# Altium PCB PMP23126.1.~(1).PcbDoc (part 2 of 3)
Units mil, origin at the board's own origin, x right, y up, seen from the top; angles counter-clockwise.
Board outline 1315.03 x 1390.8 mil, 6 copper layers (Top Layer, MidLayer1, MidLayer2, MidLayer3, MidLayer4, Bottom Layer), stack 78 mil thick; 49 components, 55 nets, 222 pads, 193 vias.
Unrouted connection lines stored in the file: 15.
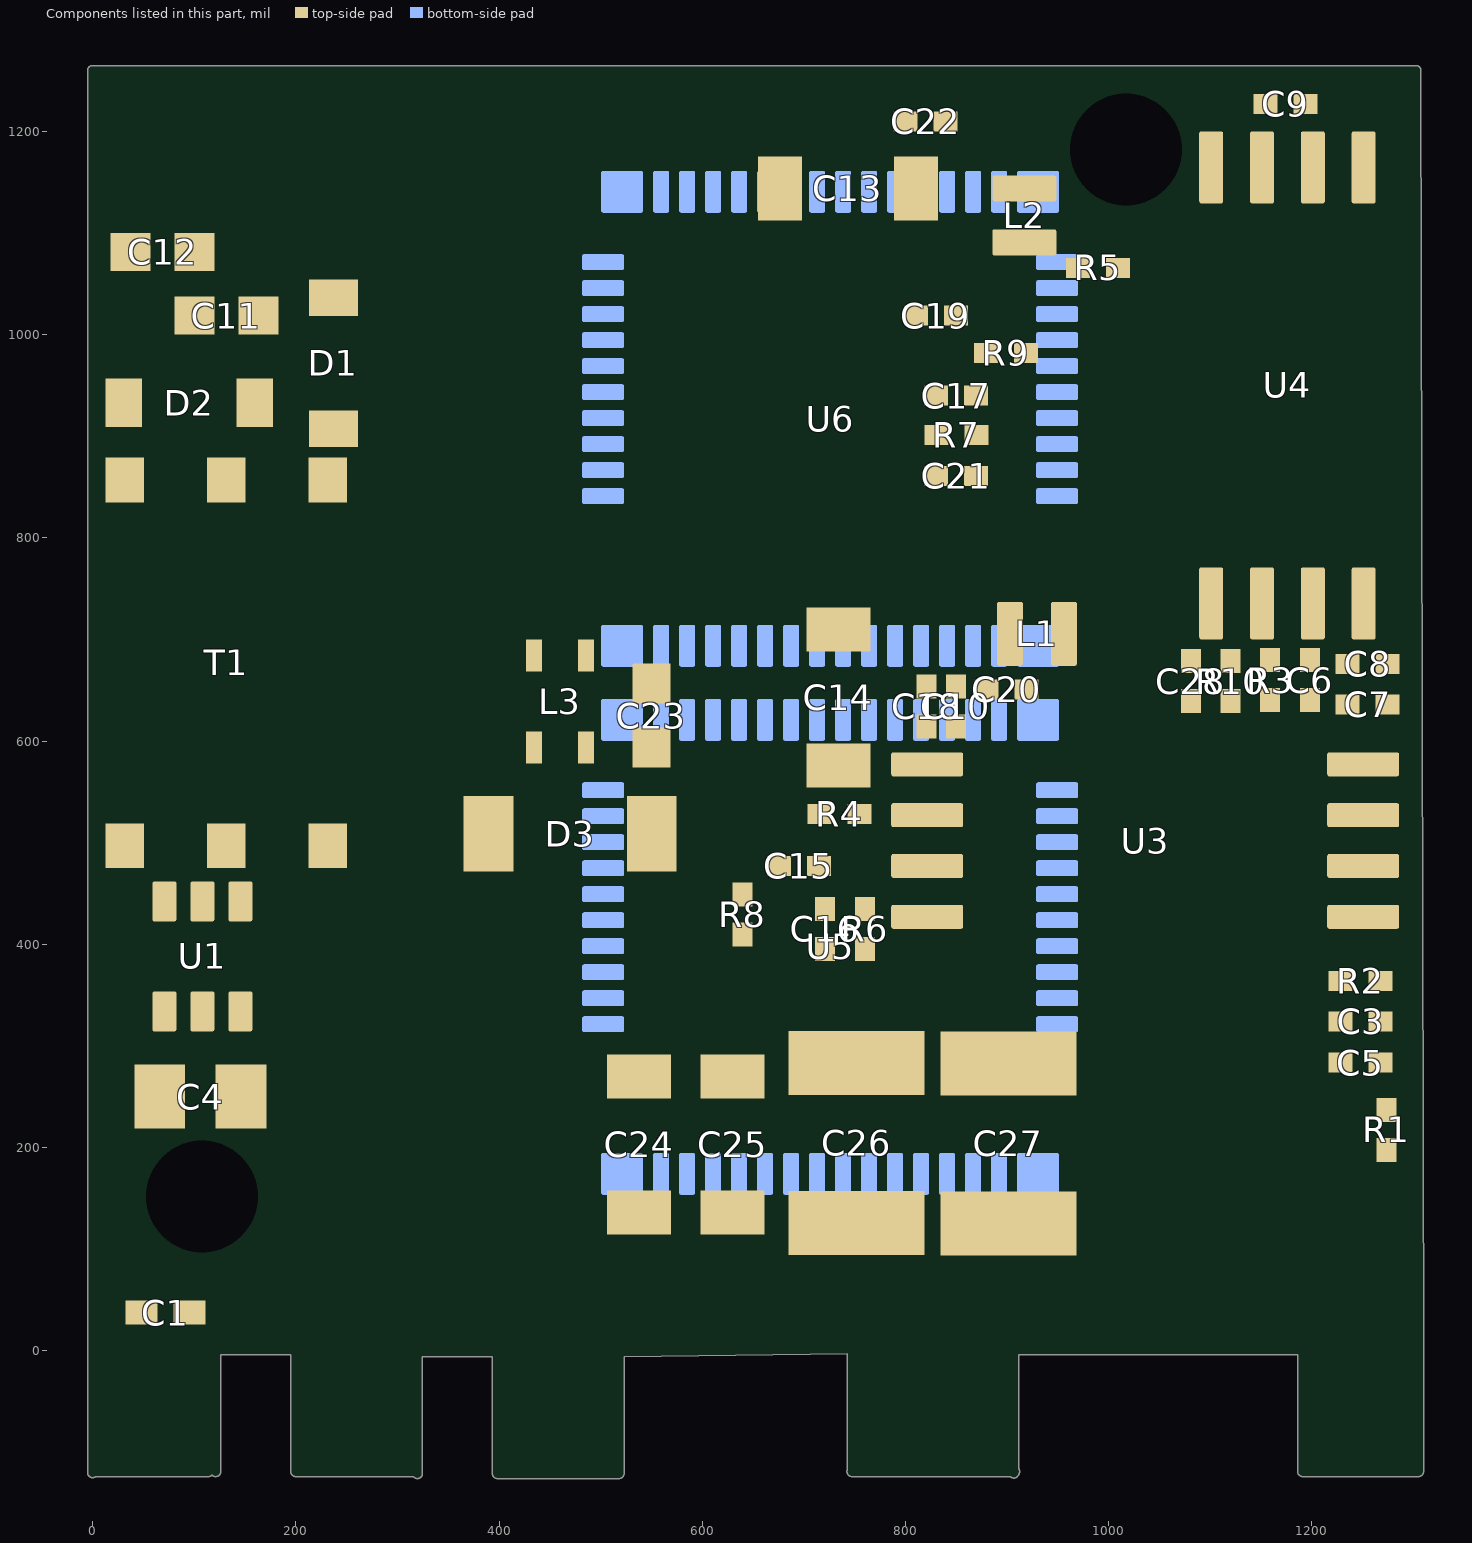
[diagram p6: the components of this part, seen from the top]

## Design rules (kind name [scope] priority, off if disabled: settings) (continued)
PolygonConnect PolygonConnect_38 [All vs IsNamedPolygon('SWNODE') Or  IsNamedPolygon('D403_2') Or  IsNamedPolygon('D403_2') Or  IsNamedPolygon('PGND') Or  IsNamedPolygon('BOTTOM_LAYER_NETC106_2_P030') Or  IsNamedPolygon('C102_1') Or  IsNamedPolygon('SGND') Or  IsNamedPolygon('TOP_LAYER_54V1_P046') Or  IsNamedPolygon('TOP_LAYER_54V2_P048') Or  IsNamedPolygon('TOP_LAYER_54V2_P048') Or  IsNamedPolygon('C108_1') Or  IsNamedPolygon('C108_1') Or  IsNamedPolygon('C108_1') Or  IsNamedPolygon('C108_1') Or  IsNamedPolygon('C108_1') Or  IsNamedPolygon('C108_1') Or  IsNamedPolygon('PGND') Or  IsNamedPolygon('ZCD') Or  IsNamedPolygon('Line') Or  IsNamedPolygon('5Vp') Or  IsNamedPolygon('12Vp') Or  IsNamedPolygon('T200_4') Or  IsNamedPolygon('T200_6') Or  IsNamedPolygon('SWNODE3') Or  IsNamedPolygon('T200_4') Or  IsNamedPolygon('T200_6') Or  IsNamedPolygon('SWNODE4') Or  IsNamedPolygon('VSR') Or  IsNamedPolygon('Iout_SNS') Or  IsNamedPolygon('SIGNAL_LAYER_2_VBB_P094') Or  IsNamedPolygon('Vbulk1') Or  IsNamedPolygon('VBB') Or  IsNamedPolygon('SIGNAL_LAYER_1_VBULK1_P106') Or  IsNamedPolygon('Line') Or  IsNamedPolygon('Line') Or  IsNamedPolygon('Line') Or  IsNamedPolygon('D404_2') Or  IsNamedPolygon('VBB') Or  IsNamedPolygon('D400_2') Or  IsNamedPolygon('SGND') Or  IsNamedPolygon('PGND') Or  IsNamedPolygon('TOP_LAYER_12VS_P126') Or  IsNamedPolygon('BOTTOM_LAYER_54V1_P128') Or  IsNamedPolygon('LEG3_HS_DRV') Or  IsNamedPolygon('LEG4_LS_DRV') Or  IsNamedPolygon('LEG4_HS_DRV') Or  IsNamedPolygon('SWNODE4') Or  IsNamedPolygon('SWNODE3') Or  IsNamedPolygon('T200_6') Or  IsNamedPolygon('T200_4') Or  IsNamedPolygon('VBB') Or  IsNamedPolygon('5Vs') Or  IsNamedPolygon('SGND') Or  IsNamedPolygon('Iout_SNS') Or  IsNamedPolygon('SGND') Or  IsNamedPolygon('SWNODE3') Or  IsNamedPolygon('SWNODE3') Or  IsNamedPolygon('SWNODE3') Or  IsNamedPolygon('SWNODE3') Or  IsNamedPolygon('SGND') Or  IsNamedPolygon('SGND') Or  IsNamedPolygon('SGND') Or  IsNamedPolygon('SWNODE4') Or  IsNamedPolygon('SWNODE4') Or  IsNamedPolygon('SWNODE4') Or  IsNamedPolygon('VSR') Or  IsNamedPolygon('SWNODE3') Or  IsNamedPolygon('SGND') Or  IsNamedPolygon('SGND') Or  IsNamedPolygon('SGND') Or  IsNamedPolygon('SGND') Or  IsNamedPolygon('SGND') Or  IsNamedPolygon('SGND') Or  IsNamedPolygon('BOTTOM_LAYER_54V1_P128') Or  IsNamedPolygon('SGND') Or  IsNamedPolygon('VSR') Or  IsNamedPolygon('C102_1') Or  IsNamedPolygon('C102_1') Or  IsNamedPolygon('C102_1') Or  IsNamedPolygon('C102_1') Or  IsNamedPolygon('C102_1') Or  IsNamedPolygon('ZCD') Or  IsNamedPolygon('PGND') Or  IsNamedPolygon('PGND') Or  IsNamedPolygon('Vbulk1') Or  IsNamedPolygon('VBB') Or  IsNamedPolygon('Vbulk1') Or  IsNamedPolygon('Vbulk1') Or  IsNamedPolygon('ZCD') Or  IsNamedPolygon('Neutral') Or  IsNamedPolygon('Neutral')] p22: connectstyle=Direct reliefconductorwidth=10 reliefentries=4 polygonreliefangle="90 Angle" airgapwidth=10
PolygonConnect PolygonConnect_37 [All vs IsNamedPolygon('SGND') Or  IsNamedPolygon('SWNODE4') Or  IsNamedPolygon('5Vp') Or  IsNamedPolygon('SWNODE4') Or  IsNamedPolygon('VBB') Or  IsNamedPolygon('Line') Or  IsNamedPolygon('SGND') Or  IsNamedPolygon('SIGNAL_LAYER_2_C102_1_P032') Or  IsNamedPolygon('TOP_LAYER_54V2_P048') Or  IsNamedPolygon('ZCD') Or  IsNamedPolygon('PGND') Or  IsNamedPolygon('SIGNAL_LAYER_2_VBB_P094') Or  IsNamedPolygon('Line') Or  IsNamedPolygon('Line') Or  IsNamedPolygon('D404_2') Or  IsNamedPolygon('PGND') Or  IsNamedPolygon('SIGNAL_LAYER_1_ZCD_P108') Or  IsNamedPolygon('SWNODE3') Or  IsNamedPolygon('SIGNAL_LAYER_4_C102_1_P038') Or  IsNamedPolygon('SWNODE3') Or  IsNamedPolygon('LEG4_HS_DRV') Or  IsNamedPolygon('SWNODE4') Or  IsNamedPolygon('5Vs') Or  IsNamedPolygon('VBB') Or  IsNamedPolygon('TOP_LAYER_54V2_P048') Or  IsNamedPolygon('C102_1') Or  IsNamedPolygon('LEG4_LS_DRV') Or  IsNamedPolygon('T200_4') Or  IsNamedPolygon('SWNODE3') Or  IsNamedPolygon('Line') Or  IsNamedPolygon('SGND') Or  IsNamedPolygon('SGND') Or  IsNamedPolygon('SWNODE4') Or  IsNamedPolygon('12Vp') Or  IsNamedPolygon('BOTTOM_LAYER_NETC106_2_P030') Or  IsNamedPolygon('T200_4') Or  IsNamedPolygon('Vbulk1') Or  IsNamedPolygon('C108_1') Or  IsNamedPolygon('BOTTOM_LAYER_54V1_P128') Or  IsNamedPolygon('BOTTOM_LAYER_54V1_P128') Or  IsNamedPolygon('SWNODE') Or  IsNamedPolygon('Iout_SNS') Or  IsNamedPolygon('VSR') Or  IsNamedPolygon('D400_2') Or  IsNamedPolygon('D403_2') Or  IsNamedPolygon('SWNODE3') Or  IsNamedPolygon('T200_6') Or  IsNamedPolygon('SWNODE3') Or  IsNamedPolygon('C108_1') Or  IsNamedPolygon('PGND') Or  IsNamedPolygon('BOTTOM_LAYER_VBULK1_P096') Or  IsNamedPolygon('BOTTOM_LAYER_54V1_P128') Or  IsNamedPolygon('TOP_LAYER_12VS_P126') Or  IsNamedPolygon('SIGNAL_LAYER_1_VBULK1_P106') Or  IsNamedPolygon('T200_4') Or  IsNamedPolygon('SGND') Or  IsNamedPolygon('C108_1') Or  IsNamedPolygon('SWNODE3') Or  IsNamedPolygon('T200_6') Or  IsNamedPolygon('T200_6') Or  IsNamedPolygon('T200_6') Or  IsNamedPolygon('SGND') Or  IsNamedPolygon('C108_1') Or  IsNamedPolygon('SGND') Or  IsNamedPolygon('VBB') Or  IsNamedPolygon('T200_4') Or  IsNamedPolygon('LEG3_HS_DRV') Or  IsNamedPolygon('C108_1') Or  IsNamedPolygon('D403_2') Or  IsNamedPolygon('Iout_SNS') Or  IsNamedPolygon('C108_1') Or  IsNamedPolygon('SWNODE4')] p23: connectstyle=Direct reliefconductorwidth=10 reliefentries=4 polygonreliefangle="90 Angle" airgapwidth=10
PolygonConnect PolygonConnect_36 [All vs IsNamedPolygon('PGND') Or  IsNamedPolygon('BOTTOM_LAYER_54V1_P128') Or  IsNamedPolygon('SGND') Or  IsNamedPolygon('LEG4_LS_DRV') Or  IsNamedPolygon('TOP_LAYER_12VS_P126') Or  IsNamedPolygon('LEG4_HS_DRV') Or  IsNamedPolygon('LEG3_HS_DRV') Or  IsNamedPolygon('SGND') Or  IsNamedPolygon('C108_1') Or  IsNamedPolygon('12Vp') Or  IsNamedPolygon('D403_2') Or  IsNamedPolygon('SIGNAL_LAYER_1_ZCD_P108') Or  IsNamedPolygon('C108_1') Or  IsNamedPolygon('BOTTOM_LAYER_VBULK1_P096') Or  IsNamedPolygon('SWNODE') Or  IsNamedPolygon('T200_4') Or  IsNamedPolygon('D400_2') Or  IsNamedPolygon('C102_1') Or  IsNamedPolygon('Line') Or  IsNamedPolygon('VBB') Or  IsNamedPolygon('Line') Or  IsNamedPolygon('TOP_LAYER_54V2_P048') Or  IsNamedPolygon('BOTTOM_LAYER_NETC106_2_P030') Or  IsNamedPolygon('SIGNAL_LAYER_1_VBULK1_P106') Or  IsNamedPolygon('Line') Or  IsNamedPolygon('5Vp') Or  IsNamedPolygon('BOTTOM_LAYER_54V1_P128') Or  IsNamedPolygon('D404_2') Or  IsNamedPolygon('C108_1') Or  IsNamedPolygon('VSR') Or  IsNamedPolygon('T200_6') Or  IsNamedPolygon('VBB') Or  IsNamedPolygon('C108_1') Or  IsNamedPolygon('SIGNAL_LAYER_2_C102_1_P032') Or  IsNamedPolygon('SGND') Or  IsNamedPolygon('PGND') Or  IsNamedPolygon('SIGNAL_LAYER_4_C102_1_P038') Or  IsNamedPolygon('Vbulk1') Or  IsNamedPolygon('TOP_LAYER_54V2_P048') Or  IsNamedPolygon('Iout_SNS') Or  IsNamedPolygon('PGND') Or  IsNamedPolygon('T200_4') Or  IsNamedPolygon('ZCD') Or  IsNamedPolygon('Line') Or  IsNamedPolygon('C108_1') Or  IsNamedPolygon('D403_2') Or  IsNamedPolygon('SIGNAL_LAYER_2_VBB_P094') Or  IsNamedPolygon('SGND') Or  IsNamedPolygon('C108_1') Or  IsNamedPolygon('SIGNAL_LAYER_1_IOUT_SNS_P044') Or  IsNamedPolygon('BOTTOM_LAYER_54V1_P128') Or  IsNamedPolygon('T200_6')] p24: connectstyle=Direct reliefconductorwidth=10 reliefentries=4 polygonreliefangle="90 Angle" airgapwidth=10
PolygonConnect PolygonConnect_35 [All vs IsNamedPolygon('SWNODE') Or  IsNamedPolygon('D403_2') Or  IsNamedPolygon('D403_2') Or  IsNamedPolygon('PGND') Or  IsNamedPolygon('BOTTOM_LAYER_NETC106_2_P030') Or  IsNamedPolygon('SIGNAL_LAYER_2_C102_1_P032') Or  IsNamedPolygon('C102_1') Or  IsNamedPolygon('SIGNAL_LAYER_4_C102_1_P038') Or  IsNamedPolygon('SGND') Or  IsNamedPolygon('SIGNAL_LAYER_1_IOUT_SNS_P044') Or  IsNamedPolygon('BOTTOM_LAYER_54V1_P128') Or  IsNamedPolygon('TOP_LAYER_54V2_P048') Or  IsNamedPolygon('BOTTOM_LAYER_54V1_P128') Or  IsNamedPolygon('TOP_LAYER_54V2_P048') Or  IsNamedPolygon('C108_1') Or  IsNamedPolygon('C108_1') Or  IsNamedPolygon('C108_1') Or  IsNamedPolygon('C108_1') Or  IsNamedPolygon('C108_1') Or  IsNamedPolygon('C108_1') Or  IsNamedPolygon('PGND') Or  IsNamedPolygon('ZCD') Or  IsNamedPolygon('Line') Or  IsNamedPolygon('5Vp') Or  IsNamedPolygon('12Vp') Or  IsNamedPolygon('T200_4') Or  IsNamedPolygon('T200_6') Or  IsNamedPolygon('SGND') Or  IsNamedPolygon('T200_4') Or  IsNamedPolygon('T200_6') Or  IsNamedPolygon('SGND') Or  IsNamedPolygon('VSR') Or  IsNamedPolygon('Iout_SNS') Or  IsNamedPolygon('SIGNAL_LAYER_2_VBB_P094') Or  IsNamedPolygon('BOTTOM_LAYER_VBULK1_P096') Or  IsNamedPolygon('Vbulk1') Or  IsNamedPolygon('VBB') Or  IsNamedPolygon('SIGNAL_LAYER_1_VBULK1_P106') Or  IsNamedPolygon('SIGNAL_LAYER_1_ZCD_P108') Or  IsNamedPolygon('Line') Or  IsNamedPolygon('Line') Or  IsNamedPolygon('Line') Or  IsNamedPolygon('D404_2') Or  IsNamedPolygon('VBB') Or  IsNamedPolygon('D400_2') Or  IsNamedPolygon('SGND') Or  IsNamedPolygon('PGND') Or  IsNamedPolygon('TOP_LAYER_12VS_P126') Or  IsNamedPolygon('BOTTOM_LAYER_54V1_P128') Or  IsNamedPolygon('LEG3_HS_DRV')] p25: connectstyle=Direct reliefconductorwidth=10 reliefentries=4 polygonreliefangle="90 Angle" airgapwidth=10
PolygonConnect PolygonConnect_34 [All vs IsNamedPolygon('SWNODE') Or  IsNamedPolygon('D403_2') Or  IsNamedPolygon('D403_2') Or  IsNamedPolygon('PGND') Or  IsNamedPolygon('BOTTOM_LAYER_NETC106_2_P030') Or  IsNamedPolygon('SIGNAL_LAYER_2_C102_1_P032') Or  IsNamedPolygon('C102_1') Or  IsNamedPolygon('SIGNAL_LAYER_4_C102_1_P038') Or  IsNamedPolygon('SGND') Or  IsNamedPolygon('SIGNAL_LAYER_1_IOUT_SNS_P044') Or  IsNamedPolygon('BOTTOM_LAYER_54V1_P128') Or  IsNamedPolygon('TOP_LAYER_54V2_P048') Or  IsNamedPolygon('BOTTOM_LAYER_54V1_P128') Or  IsNamedPolygon('TOP_LAYER_54V2_P048') Or  IsNamedPolygon('C108_1') Or  IsNamedPolygon('C108_1') Or  IsNamedPolygon('C108_1') Or  IsNamedPolygon('C108_1') Or  IsNamedPolygon('C108_1') Or  IsNamedPolygon('C108_1') Or  IsNamedPolygon('PGND') Or  IsNamedPolygon('ZCD') Or  IsNamedPolygon('Line') Or  IsNamedPolygon('5Vp') Or  IsNamedPolygon('12Vp') Or  IsNamedPolygon('T200_4') Or  IsNamedPolygon('T200_6') Or  IsNamedPolygon('SGND') Or  IsNamedPolygon('T200_4') Or  IsNamedPolygon('T200_6') Or  IsNamedPolygon('SGND') Or  IsNamedPolygon('VSR') Or  IsNamedPolygon('Iout_SNS') Or  IsNamedPolygon('SIGNAL_LAYER_2_VBB_P094') Or  IsNamedPolygon('BOTTOM_LAYER_VBULK1_P096') Or  IsNamedPolygon('Vbulk1') Or  IsNamedPolygon('VBB') Or  IsNamedPolygon('SIGNAL_LAYER_1_VBULK1_P106') Or  IsNamedPolygon('SIGNAL_LAYER_1_ZCD_P108') Or  IsNamedPolygon('Line') Or  IsNamedPolygon('Line') Or  IsNamedPolygon('Line') Or  IsNamedPolygon('D404_2') Or  IsNamedPolygon('VBB') Or  IsNamedPolygon('D400_2') Or  IsNamedPolygon('SGND')] p26: connectstyle=Direct reliefconductorwidth=10 reliefentries=4 polygonreliefangle="90 Angle" airgapwidth=10
PolygonConnect PolygonConnect_33 [All vs IsNamedPolygon('SIGNAL_LAYER_1_VBULK1_P106')] p27: connectstyle=Direct reliefconductorwidth=10 reliefentries=4 polygonreliefangle="90 Angle" airgapwidth=10
PolygonConnect PolygonConnect_32 [All vs IsNamedPolygon('SIGNAL_LAYER_1_VBULK1_P106')] p28: connectstyle=Direct reliefconductorwidth=10 reliefentries=4 polygonreliefangle="90 Angle" airgapwidth=10
PolygonConnect PolygonConnect_31 [All vs IsNamedPolygon('SIGNAL_LAYER_1_VBULK1_P106')] p29: connectstyle=Direct reliefconductorwidth=10 reliefentries=4 polygonreliefangle="90 Angle" airgapwidth=10
PolygonConnect PolygonConnect_30 [All vs IsNamedPolygon('VBB')] p30: connectstyle=Direct reliefconductorwidth=10 reliefentries=4 polygonreliefangle="90 Angle" airgapwidth=10
PolygonConnect PolygonConnect_29 [All vs IsNamedPolygon('SGND')] p31: connectstyle=Direct reliefconductorwidth=10 reliefentries=4 polygonreliefangle="90 Angle" airgapwidth=10
PolygonConnect PolygonConnect_28 [All vs IsNamedPolygon('Vbulk1')] p32: connectstyle=Direct reliefconductorwidth=10 reliefentries=4 polygonreliefangle="90 Angle" airgapwidth=10
PolygonConnect PolygonConnect_27 [All vs IsNamedPolygon('BOTTOM_LAYER_VBULK1_P096')] p33: connectstyle=Direct reliefconductorwidth=10 reliefentries=4 polygonreliefangle="90 Angle" airgapwidth=10
PolygonConnect PolygonConnect_26 [All vs IsNamedPolygon('SIGNAL_LAYER_2_VBB_P094')] p34: connectstyle=Direct reliefconductorwidth=10 reliefentries=4 polygonreliefangle="90 Angle" airgapwidth=10
PolygonConnect PolygonConnect_25 [All vs IsNamedPolygon('C108_1')] p35: connectstyle=Direct reliefconductorwidth=10 reliefentries=4 polygonreliefangle="90 Angle" airgapwidth=10
PolygonConnect PolygonConnect_24 [All vs IsNamedPolygon('BOTTOM_LAYER_EARTH_P100')] p36: connectstyle=Direct reliefconductorwidth=10 reliefentries=4 polygonreliefangle="90 Angle" airgapwidth=10
PolygonConnect PolygonConnect_23 [All vs IsNamedPolygon('BOTTOM_LAYER_54V1_P128')] p37: connectstyle=Direct reliefconductorwidth=10 reliefentries=4 polygonreliefangle="90 Angle" airgapwidth=10
PolygonConnect PolygonConnect_22 [All vs IsNamedPolygon('BOTTOM_LAYER_VBULK1_P096')] p38: connectstyle=Direct reliefconductorwidth=10 reliefentries=4 polygonreliefangle="90 Angle" airgapwidth=10
PolygonConnect PolygonConnect_21 [All vs IsNamedPolygon('SIGNAL_LAYER_2_VBB_P094')] p39: connectstyle=Direct reliefconductorwidth=10 reliefentries=4 polygonreliefangle="90 Angle" airgapwidth=10
PolygonConnect PolygonConnect_20 [All vs IsNamedPolygon('Iout_SNS')] p40: connectstyle=Direct reliefconductorwidth=10 reliefentries=4 polygonreliefangle="90 Angle" airgapwidth=10
PolygonConnect PolygonConnect_19 [All vs IsNamedPolygon('C108_1') Or  IsNamedPolygon('BOTTOM_LAYER_NETC106_2_P030') Or  IsNamedPolygon('D403_2') Or  IsNamedPolygon('C102_1') Or  IsNamedPolygon('SWNODE') Or  IsNamedPolygon('D403_2') Or  IsNamedPolygon('SIGNAL_LAYER_4_C102_1_P038') Or  IsNamedPolygon('PGND') Or  IsNamedPolygon('SIGNAL_LAYER_2_C102_1_P032') Or  IsNamedPolygon('SIGNAL_LAYER_1_IOUT_SNS_P044') Or  IsNamedPolygon('SGND') Or  IsNamedPolygon('C108_1') Or  IsNamedPolygon('BOTTOM_LAYER_54V1_P128') Or  IsNamedPolygon('C108_1') Or  IsNamedPolygon('C108_1') Or  IsNamedPolygon('TOP_LAYER_54V2_P048') Or  IsNamedPolygon('BOTTOM_LAYER_54V1_P128') Or  IsNamedPolygon('TOP_LAYER_54V2_P048') Or  IsNamedPolygon('C108_1') Or  IsNamedPolygon('C108_1') Or  IsNamedPolygon('12Vp') Or  IsNamedPolygon('5Vp') Or  IsNamedPolygon('Line') Or  IsNamedPolygon('T200_4') Or  IsNamedPolygon('SGND') Or  IsNamedPolygon('VSR') Or  IsNamedPolygon('ZCD') Or  IsNamedPolygon('PGND') Or  IsNamedPolygon('T200_6') Or  IsNamedPolygon('Neutral') Or  IsNamedPolygon('T200_4') Or  IsNamedPolygon('SGND') Or  IsNamedPolygon('T200_6')] p41: connectstyle=Direct reliefconductorwidth=10 reliefentries=4 polygonreliefangle="90 Angle" airgapwidth=10
PolygonConnect PolygonConnect_18 [All vs IsNamedPolygon('SWNODE') Or  IsNamedPolygon('D403_2') Or  IsNamedPolygon('D403_2') Or  IsNamedPolygon('PGND') Or  IsNamedPolygon('BOTTOM_LAYER_NETC106_2_P030') Or  IsNamedPolygon('SIGNAL_LAYER_2_C102_1_P032') Or  IsNamedPolygon('C102_1') Or  IsNamedPolygon('SIGNAL_LAYER_4_C102_1_P038') Or  IsNamedPolygon('SGND') Or  IsNamedPolygon('SIGNAL_LAYER_1_IOUT_SNS_P044') Or  IsNamedPolygon('BOTTOM_LAYER_54V1_P128') Or  IsNamedPolygon('TOP_LAYER_54V2_P048') Or  IsNamedPolygon('BOTTOM_LAYER_54V1_P128') Or  IsNamedPolygon('TOP_LAYER_54V2_P048') Or  IsNamedPolygon('C108_1') Or  IsNamedPolygon('C108_1') Or  IsNamedPolygon('C108_1') Or  IsNamedPolygon('C108_1') Or  IsNamedPolygon('C108_1') Or  IsNamedPolygon('C108_1') Or  IsNamedPolygon('Neutral') Or  IsNamedPolygon('PGND') Or  IsNamedPolygon('ZCD') Or  IsNamedPolygon('Line') Or  IsNamedPolygon('5Vp') Or  IsNamedPolygon('12Vp') Or  IsNamedPolygon('T200_4') Or  IsNamedPolygon('T200_6') Or  IsNamedPolygon('SGND') Or  IsNamedPolygon('T200_4') Or  IsNamedPolygon('T200_6') Or  IsNamedPolygon('SGND')] p42: connectstyle=Direct reliefconductorwidth=10 reliefentries=4 polygonreliefangle="90 Angle" airgapwidth=10
PolygonConnect PolygonConnect_17 [All vs IsNamedPolygon('12Vp') Or  IsNamedPolygon('T200_4') Or  IsNamedPolygon('T200_6') Or  IsNamedPolygon('SGND') Or  IsNamedPolygon('TOP_LAYER_54V2_P048') Or  IsNamedPolygon('SIGNAL_LAYER_1_IOUT_SNS_P044') Or  IsNamedPolygon('BOTTOM_LAYER_54V1_P128') Or  IsNamedPolygon('SGND') Or  IsNamedPolygon('C102_1') Or  IsNamedPolygon('SIGNAL_LAYER_4_C102_1_P038') Or  IsNamedPolygon('Neutral') Or  IsNamedPolygon('C108_1') Or  IsNamedPolygon('C108_1') Or  IsNamedPolygon('C108_1') Or  IsNamedPolygon('BOTTOM_LAYER_54V1_P128') Or  IsNamedPolygon('TOP_LAYER_54V2_P048') Or  IsNamedPolygon('SIGNAL_LAYER_2_C102_1_P032') Or  IsNamedPolygon('SWNODE') Or  IsNamedPolygon('C108_1') Or  IsNamedPolygon('C108_1') Or  IsNamedPolygon('C108_1') Or  IsNamedPolygon('D403_2') Or  IsNamedPolygon('BOTTOM_LAYER_NETC106_2_P030') Or  IsNamedPolygon('PGND') Or  IsNamedPolygon('D403_2') Or  IsNamedPolygon('5Vp') Or  IsNamedPolygon('PGND') Or  IsNamedPolygon('ZCD') Or  IsNamedPolygon('Line')] p43: connectstyle=Direct reliefconductorwidth=10 reliefentries=4 polygonreliefangle="90 Angle" airgapwidth=10
PolygonConnect PolygonConnect_16 [All vs IsNamedPolygon('D403_2') Or  IsNamedPolygon('C102_1') Or  IsNamedPolygon('C108_1') Or  IsNamedPolygon('SWNODE') Or  IsNamedPolygon('BOTTOM_LAYER_54V1_P128') Or  IsNamedPolygon('SGND') Or  IsNamedPolygon('Line') Or  IsNamedPolygon('ZCD') Or  IsNamedPolygon('SIGNAL_LAYER_1_IOUT_SNS_P044') Or  IsNamedPolygon('Neutral') Or  IsNamedPolygon('PGND') Or  IsNamedPolygon('12Vp') Or  IsNamedPolygon('C108_1') Or  IsNamedPolygon('C108_1') Or  IsNamedPolygon('TOP_LAYER_54V2_P048') Or  IsNamedPolygon('C108_1') Or  IsNamedPolygon('TOP_LAYER_54V2_P048') Or  IsNamedPolygon('T200_4') Or  IsNamedPolygon('T200_6') Or  IsNamedPolygon('D403_2') Or  IsNamedPolygon('C108_1') Or  IsNamedPolygon('C108_1') Or  IsNamedPolygon('SIGNAL_LAYER_4_C102_1_P038') Or  IsNamedPolygon('SIGNAL_LAYER_2_C102_1_P032') Or  IsNamedPolygon('PGND') Or  IsNamedPolygon('BOTTOM_LAYER_NETC106_2_P030') Or  IsNamedPolygon('5Vp') Or  IsNamedPolygon('BOTTOM_LAYER_54V1_P128')] p44: connectstyle=Direct reliefconductorwidth=10 reliefentries=4 polygonreliefangle="90 Angle" airgapwidth=10
PolygonConnect PolygonConnect_15 [All vs IsNamedPolygon('SWNODE') Or  IsNamedPolygon('D403_2') Or  IsNamedPolygon('D403_2') Or  IsNamedPolygon('SIGNAL_LAYER_1_PGND_P018') Or  IsNamedPolygon('PGND') Or  IsNamedPolygon('BOTTOM_LAYER_NETC106_2_P030') Or  IsNamedPolygon('SIGNAL_LAYER_2_C102_1_P032') Or  IsNamedPolygon('C102_1') Or  IsNamedPolygon('SIGNAL_LAYER_4_C102_1_P038') Or  IsNamedPolygon('SGND') Or  IsNamedPolygon('SIGNAL_LAYER_1_IOUT_SNS_P044') Or  IsNamedPolygon('BOTTOM_LAYER_54V1_P128') Or  IsNamedPolygon('TOP_LAYER_54V2_P048') Or  IsNamedPolygon('BOTTOM_LAYER_54V1_P128') Or  IsNamedPolygon('TOP_LAYER_54V2_P048') Or  IsNamedPolygon('C108_1') Or  IsNamedPolygon('C108_1') Or  IsNamedPolygon('C108_1') Or  IsNamedPolygon('C108_1') Or  IsNamedPolygon('C108_1') Or  IsNamedPolygon('C108_1') Or  IsNamedPolygon('Neutral') Or  IsNamedPolygon('PGND') Or  IsNamedPolygon('ZCD') Or  IsNamedPolygon('Line') Or  IsNamedPolygon('5Vp') Or  IsNamedPolygon('12Vp')] p45: connectstyle=Direct reliefconductorwidth=10 reliefentries=4 polygonreliefangle="90 Angle" airgapwidth=10
PolygonConnect PolygonConnect_14 [All vs IsNamedPolygon('TOP_LAYER_54V2_P048') Or  IsNamedPolygon('C108_1') Or  IsNamedPolygon('C108_1') Or  IsNamedPolygon('SIGNAL_LAYER_4_C102_1_P038') Or  IsNamedPolygon('C102_1') Or  IsNamedPolygon('SIGNAL_LAYER_2_C102_1_P032') Or  IsNamedPolygon('SIGNAL_LAYER_1_PGND_P018') Or  IsNamedPolygon('SIGNAL_LAYER_1_IOUT_SNS_P044') Or  IsNamedPolygon('SGND') Or  IsNamedPolygon('C108_1') Or  IsNamedPolygon('ZCD') Or  IsNamedPolygon('PGND') Or  IsNamedPolygon('TOP_LAYER_54V2_P048') Or  IsNamedPolygon('BOTTOM_LAYER_NETC106_2_P030') Or  IsNamedPolygon('PGND') Or  IsNamedPolygon('C108_1') Or  IsNamedPolygon('C108_1') Or  IsNamedPolygon('D403_2') Or  IsNamedPolygon('Line') Or  IsNamedPolygon('C108_1') Or  IsNamedPolygon('Neutral') Or  IsNamedPolygon('SWNODE') Or  IsNamedPolygon('D403_2') Or  IsNamedPolygon('BOTTOM_LAYER_54V1_P128') Or  IsNamedPolygon('BOTTOM_LAYER_54V1_P128')] p46: connectstyle=Direct reliefconductorwidth=10 reliefentries=4 polygonreliefangle="90 Angle" airgapwidth=10
PolygonConnect PolygonConnect_13 [All vs IsNamedPolygon('PGND') Or  IsNamedPolygon('D403_2') Or  IsNamedPolygon('SIGNAL_LAYER_1_PGND_P018') Or  IsNamedPolygon('D403_2') Or  IsNamedPolygon('SWNODE') Or  IsNamedPolygon('SGND') Or  IsNamedPolygon('BOTTOM_LAYER_54V1_P128') Or  IsNamedPolygon('C108_1') Or  IsNamedPolygon('SIGNAL_LAYER_4_C102_1_P038') Or  IsNamedPolygon('C108_1') Or  IsNamedPolygon('TOP_LAYER_54V2_P048') Or  IsNamedPolygon('TOP_LAYER_54V2_P048') Or  IsNamedPolygon('C108_1') Or  IsNamedPolygon('C108_1') Or  IsNamedPolygon('C108_1') Or  IsNamedPolygon('BOTTOM_LAYER_NETC106_2_P030') Or  IsNamedPolygon('SIGNAL_LAYER_1_IOUT_SNS_P044') Or  IsNamedPolygon('C108_1') Or  IsNamedPolygon('C102_1') Or  IsNamedPolygon('SIGNAL_LAYER_2_C102_1_P032') Or  IsNamedPolygon('BOTTOM_LAYER_54V1_P128')] p47: connectstyle=Direct reliefconductorwidth=10 reliefentries=4 polygonreliefangle="90 Angle" airgapwidth=10
PolygonConnect PolygonConnect_12 [All vs IsNamedPolygon('TOP_LAYER_54V2_P048')] p48: connectstyle=Direct reliefconductorwidth=10 reliefentries=4 polygonreliefangle="90 Angle" airgapwidth=10
PolygonConnect PolygonConnect_11 [All vs IsNamedPolygon('BOTTOM_LAYER_54V1_P128')] p49: connectstyle=Direct reliefconductorwidth=10 reliefentries=4 polygonreliefangle="90 Angle" airgapwidth=10
PolygonConnect PolygonConnect_10 [All vs IsNamedPolygon('SIGNAL_LAYER_1_IOUT_SNS_P044')] p50: thpad.connectstyle=Direct thpad.reliefconductorwidth=10 thpad.reliefentries=4 thpad.polygonreliefangle="90 Angle" thpad.airgapwidth=10 smdpad.connectstyle=Relief smdpad.reliefconductorwidth=10 smdpad.reliefentries=4 smdpad.polygonreliefangle="90 Angle" smdpad.airgapwidth=10 via.connectstyle=Direct via.reliefconductorwidth=10 via.reliefentries=4 via.polygonreliefangle="90 Angle" via.airgapwidth=10
PolygonConnect PolygonConnect_9 [All vs IsNamedPolygon('SGND')] p51: thpad.connectstyle=Direct thpad.reliefconductorwidth=10 thpad.reliefentries=4 thpad.polygonreliefangle="90 Angle" thpad.airgapwidth=10 smdpad.connectstyle=Relief smdpad.reliefconductorwidth=10 smdpad.reliefentries=4 smdpad.polygonreliefangle="90 Angle" smdpad.airgapwidth=10 via.connectstyle=Direct via.reliefconductorwidth=10 via.reliefentries=4 via.polygonreliefangle="90 Angle" via.airgapwidth=10
PolygonConnect PolygonConnect_8 [All vs IsNamedPolygon('SGND')] p52: thpad.connectstyle=Direct thpad.reliefconductorwidth=10 thpad.reliefentries=4 thpad.polygonreliefangle="90 Angle" thpad.airgapwidth=10 smdpad.connectstyle=Relief smdpad.reliefconductorwidth=10 smdpad.reliefentries=4 smdpad.polygonreliefangle="90 Angle" smdpad.airgapwidth=10 via.connectstyle=Direct via.reliefconductorwidth=10 via.reliefentries=4 via.polygonreliefangle="90 Angle" via.airgapwidth=10
PolygonConnect PolygonConnect_7 [All vs IsNamedPolygon('SGND')] p53: thpad.connectstyle=Relief thpad.reliefconductorwidth=0 thpad.reliefentries=4 thpad.polygonreliefangle="90 Angle" thpad.airgapwidth=0 smdpad.connectstyle=Relief smdpad.reliefconductorwidth=10 smdpad.reliefentries=4 smdpad.polygonreliefangle="90 Angle" smdpad.airgapwidth=10 via.connectstyle=Relief via.reliefconductorwidth=10 via.reliefentries=4 via.polygonreliefangle="90 Angle" via.airgapwidth=10
PolygonConnect PolygonConnect_6 [All vs IsNamedPolygon('SGND')] p54: thpad.connectstyle=Direct thpad.reliefconductorwidth=10 thpad.reliefentries=4 thpad.polygonreliefangle="90 Angle" thpad.airgapwidth=10 smdpad.connectstyle=Relief smdpad.reliefconductorwidth=10 smdpad.reliefentries=4 smdpad.polygonreliefangle="90 Angle" smdpad.airgapwidth=10 via.connectstyle=Relief via.reliefconductorwidth=10 via.reliefentries=4 via.polygonreliefangle="90 Angle" via.airgapwidth=10
PolygonConnect PolygonConnect_5 [All vs IsNamedPolygon('SGND')] p55: thpad.connectstyle=Direct thpad.reliefconductorwidth=10 thpad.reliefentries=4 thpad.polygonreliefangle="90 Angle" thpad.airgapwidth=10 smdpad.connectstyle=Relief smdpad.reliefconductorwidth=10 smdpad.reliefentries=4 smdpad.polygonreliefangle="90 Angle" smdpad.airgapwidth=10 via.connectstyle=Relief via.reliefconductorwidth=10 via.reliefentries=4 via.polygonreliefangle="90 Angle" via.airgapwidth=10
PolygonConnect PolygonConnect_4 [All vs IsNamedPolygon('SIGNAL_LAYER_1_PGND_P018') Or  IsNamedPolygon('SWNODE') Or  IsNamedPolygon('D403_2') Or  IsNamedPolygon('SIGNAL_LAYER_4_C102_1_P038') Or  IsNamedPolygon('D403_2') Or  IsNamedPolygon('BOTTOM_LAYER_NETC106_2_P030') Or  IsNamedPolygon('C102_1') Or  IsNamedPolygon('PGND') Or  IsNamedPolygon('SIGNAL_LAYER_2_C102_1_P032')] p56: connectstyle=Direct reliefconductorwidth=10 reliefentries=4 polygonreliefangle="90 Angle" airgapwidth=10
PolygonConnect PolygonConnect_3 [All vs IsNamedPolygon('SWNODE') Or  IsNamedPolygon('D403_2') Or  IsNamedPolygon('Neutral') Or  IsNamedPolygon('C106_2') Or  IsNamedPolygon('D403_2') Or  IsNamedPolygon('Neutral') Or  IsNamedPolygon('Neutral')] p57: connectstyle=Direct reliefconductorwidth=10 reliefentries=4 polygonreliefangle="90 Angle" airgapwidth=10
PolygonConnect PolygonConnect_2 [All vs IsNamedPolygon('Neutral') Or  IsNamedPolygon('Neutral') Or  IsNamedPolygon('C106_2') Or  IsNamedPolygon('SWNODE') Or  IsNamedPolygon('Neutral')] p58: connectstyle=Direct reliefconductorwidth=10 reliefentries=4 polygonreliefangle="90 Angle" airgapwidth=10
PolygonConnect PolygonConnect_1 [All vs IsNamedPolygon('Neutral') Or  IsNamedPolygon('Neutral')] p59: connectstyle=Direct reliefconductorwidth=10 reliefentries=4 polygonreliefangle="90 Angle" airgapwidth=10
PolygonConnect [All] p60: connectstyle=Direct reliefconductorwidth=10 reliefentries=4 polygonreliefangle="90 Angle" airgapwidth=10
RoutingVias ThermalPadVias [IsVia and InAnyComponent] p1: holewidth=7.87 width=19.68 viastyle="Through Hole" minholewidth=7.87 minwidth=19.68 maxholewidth=12.99 maxwidth=23.62
RoutingVias [All] p2: holewidth=10 width=34 viastyle="Through Hole" minholewidth=7.87 minwidth=19 maxholewidth=40 maxwidth=65
SilkToSilkClearance SilkToSilkClearance_Pb-FreeLogo [(HasFootprint('Pb-Free_Overlay_Medium') OR HasFootprint('Pb-Free_Overlay_Small')) vs (HasFootprint('Pb-Free_Overlay_Medium') OR HasFootprint('Pb-Free_Overlay_Small'))] p1: silktosilkclearance=0
SilkToSilkClearance [All] p2: silktosilkclearance=1
SilkToSolderMaskClearance SilkToComponentPadClearance [(IsPad or IsFill or IsRegion) and InAnycomponent] p1: minsilkscreentomaskgap=1 clearancetoexposedcopper=TRUE
SilkToSolderMaskClearance "Silk to Solder Mask Opening" [All] p2: minsilkscreentomaskgap=1 clearancetoexposedcopper=FALSE
SolderMaskExpansion [All] p1: expansion=1.97
Width [All] p1: maxlimit=100 minlimit=6 preferedwidth=10 checkconnectedcopper=TRUE
14 further rules are at their usual default settings.

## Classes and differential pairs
net class INGND: 3.3Vs _Bot_FET_FAULT1 _Top_FET_FAULT1 AGND LEG1_HS LEG1_LS NetC5_1 NetC6_1 NetR2_2 NetR10_2 NetU2_12 NetU3_12
net class PGND: 5V_L1 5Vp 12V FAULT_LS NetC17_2 NetC19_2 NetC22_1 NetL2_2 NetR5_1 NetR9_2 NetT1_4 NetT1_6 NetU2_5 NetU6_43 NetU6_47 NetU6_48 NetU6_52 PGND PGND_NC1 PGND_NC2 PGND_NC3 PGND_NC4 PGND_NC5 TEMP_LS
net class VHV: Vbulk+ VHV_NC1 VHV_NC2
net class VSW1NET: 5V_H1 12V ISO_12V_H1 NCT1 NetC11_1 NetC11_2 NetC12_2 NetC15_2 NetC16_2 NetC20_1 NetD1_2 NetL1_2 NetR4_2 NetR8_2 NetT1_5 NetU3_3 NetU3_5 NetU5_43 NetU5_47 NetU5_48 NetU5_52 SW1 SW1_NC1 SW1_NC2 SW1_NC3 SW1_NC4 SW1_NC5 SW1_NC6 SW1_NC7 TEMP_HS_NC1
component class LMG352X: U5 U6

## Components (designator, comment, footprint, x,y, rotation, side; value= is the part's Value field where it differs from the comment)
C1 "C1005X7R1H104K050BB" 0402 71.69,37.41 r0 top value=0.1uF
C3 "C1005C0G1H680J050BA" 0402L 1248,324.09 r180 top value=68pF
C4 "GCM21BR71C475KA73L" 0805_HV 106,250 r0 top value=4.7uF
C5 "04025A101FAT2A" 0402L 1247.9,283.5 r180 top value=100pF
C6 "04025A101FAT2A" 0402L 1198,660 r270 top value=100pF
C7 "C1005X7R1H104K050BB" 0402L 1255,636 r180 top value=0.1uF
C8 "C1005X7R1H104K050BB" 0402L 1255,676 r0 top value=0.1uF
C9 "C1005X7R1H104K050BB" 0402L 1174,1227 r0 top value=0.1uF
C10 "C1005X7R1H104K050BB" 0402L 849.62,634 r90 top value=0.1uF
C11 "C1608X5R1V475K080AC" 0603 131.62,1018.63 r180 top value=4.7uF
C12 "C1608X5R1V475K080AC" 0603 68.88,1081.48 r180 top value=4.7uF
C13 "C3216X7R1E106M160AE" 1206_190 743.36,1143.96 r180 top value=10uF
C14 "C3216X7R1E106M160AE" 1206_190 734,643 r90 top value=10uF
C15 "04025A101FAT2A" 0402L 695.25,477 r0 top value=100pF
C16 "04025A101FAT2A" 0402L 720.95,415 r270 top value=100pF
C17 "04025A101FAT2A" 0402L 850,940 r0 top value=100pF
C18 "CL05B224KO5NNNC" 0402L 820.93,634 r270 top value=0.22uF
C19 "04025A101FAT2A" 0402L 829.94,1018.63 r0 top value=100pF
C20 "GRT155R61E225KE13D" 0402L 899.5,650.82 r180 top value=2.2uF
C21 "CL05B224KO5NNNC" 0402L 850,861 r0 top value=0.22uF
C22 "GRT155R61E225KE13D" 0402L 820,1210 r180 top value=2.2uF
C23 "C1608X5R1V475K080AC" 0603 550,625 r90 top value=4.7uF
C24 "C1206C223KDRACTU" 1206_190 538,203 r90 top value=0.022uF
C25 "C1206C223KDRACTU" 1206_190 630,203 r90 top value=0.022uF
C26 "C1812W104KDRACTU" 1812_254 752,204.48 r90 top value=0.1uF
C27 "C1812W104KDRACTU" 1812_254 901.45,204 r90 top value=0.1uF
C28 "C1005C0G1H680J050BA" 0402L 1081,659 r90 top value=68pF
D1 "MBR0520LT1G" SOD-123 237,972 r270 top value=20V
D2 "MBR0520LT1G" SOD-123 95,933 r180 top value=20V
D3 "ES1JAF" SMAF 470,508.64 r180 top value=600V
L1 "SDEM20161T-4R7MS" FP-SDEM20161T-4R7MS_SMD2-MFG 929.44,705.4 r0 top
L2 "SDEM20161T-4R7MS" FP-SDEM20161T-4R7MS_SMD2-MFG 917.03,1117.39 r90 top
L3 "ACM2520-601-2P-T002" TDK_ACM2520-2P 460,639.13 r270 top
R1 "RC0402FR-0749R9L" 0402L 1273.29,217.19 r90 top value=49.9
R2 "CRCW0402300RJNED" 0402L 1247.9,364 r180 top value=300
R3 "RC0402FR-0749R9L" 0402L 1159,660 r90 top value=49.9
R4 "RC0402FR-0749R9L" 0402L 735,528 r0 top value=49.9
R5 "RC0402FR-0749R9L" 0402L 989.48,1065.72 r180 top value=49.9
R6 "ERJ-2RKF2003X" 0402L 760,415 r270 top value=200k
R7 "ERJ-2RKF2003X" 0402L 850.08,901.07 r0 top value=200k
R8 "ERJ-2GE0R00X" 0402L 639.59,429.42 r270 top value=0
R9 "ERJ-2GE0R00X" 0402L 899,982 r0 top value=0
R10 "CRCW0402300RJNED" 0402L 1120,659 r90 top value=300
T1 "760390014" Wurth_760390013 131.62,677 r270 top value=475uH
U1 "SN6505BDBVR" DBV0006A_N 108.09,388 r90 top
U3 "ISO7721FDWV" DWV0008A 1036,502 r0 top
U4 "ISO7721FDWV" DWV0008A 1176,950 r270 top
U5 "XMG3522R030QRQSTQ1" RQS0052A-MFG 725.84,397.43 r90 bottom
U6 "XMG3522R030QRQSTQ1" RQS0052A-MFG 725.84,917.17 r90 bottom

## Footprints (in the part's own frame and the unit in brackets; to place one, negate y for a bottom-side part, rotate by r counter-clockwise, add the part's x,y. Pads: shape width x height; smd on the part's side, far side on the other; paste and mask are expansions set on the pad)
0402 [mm] "0402 from SM-752 data"
  rect 0.8x0.6 smd: 1(-0.6,0) 2(0.6,0)
  silkscreen extent -1.22,-0.52 1.22,0.52, body extent -0.55,-0.3 0.55,0.3, height 0.6
0402L [mm] "0402 from SM-752 data"
  rect 0.6x0.5 smd: 1(-0.5,0) 2(0.5,0)
  body extent -0.55,-0.3 0.55,0.3, height 0.6
0603 [mm] "0603 from SM-752 data"
  rect 1x0.95 smd: 1(-0.8,0) 2(0.8,0)
  silkscreen extent -1.52,-0.69 1.52,0.69, body extent -0.87,-0.47 0.87,0.47, height 1
0805_HV [mil] "0805 with 30mil clearance between pads"
  rect 50x63 smd: 1(-40,0) 2(40,0)
  silkscreen extent -74,-40 74,40, body extent -43,-29 43,29, height 57
1206_190 [mm] "1206_190"
  rect 1.1x1.6 smd: 1(-1.7,0) 2(1.7,0)
  silkscreen extent -0.9,-1 0.9,1, body extent -1.75,-0.95 1.75,0.95, height 1.9
1812_254 [mm] "SMD, 2-Leads, Body 4.8x3.4mm"
  rect 1.6x3.4 smd: 1(-2,0) 2(2,0)
  silkscreen extent -0.8,-1.7 0.8,1.7, body extent -2.4,-1.7 2.4,1.7, height 2.54
DBV0006A_N [mm] "SOT23, 6-Leads, Body 2.9x1.6mm, Pitch 0.95mm, Lead Span 2.8mm, IPC Medium Density"
  rrect17% 1x0.6 smd: 1(-1.375,0.95) 2(-1.375,0) 3(-1.375,-0.95) 4(1.375,-0.95) 5(1.375,0) 6(1.375,0.95)
  silkscreen extent -1.68,-1.55 0.5,1.55, body extent -1.42,-1.46 1.42,1.46, height 1.12
DWV0008A [mm] "SOIC, 8-Leads, Body 5.95x7.6mm (max), Pitch 1.27mm"
  rrect17% 1.8x0.6 smd: 1(-5.45,1.905) 2(-5.45,0.635) 3(-5.45,-0.635) 4(-5.45,-1.905) 5(5.45,-1.905) 6(5.45,-0.635) 7(5.45,0.635) 8(5.45,1.905)
  silkscreen extent -6.25,-2.95 2.98,2.95, body extent -5.77,-2.92 5.77,2.93, height 2.67
FP-SDEM20161T-4R7MS_SMD2-MFG [mm]
  rrect15% 0.65x1.6 smd paste+0 mask+0: 1(-0.675,0) 2(0.675,0)
  silkscreen extent -1.05,-1.22 1.05,1.2, body extent -1,-0.8 1,0.8, height 1
RQS0052A-MFG [mm]
  rrect10% 1.05x1.05 smd paste+0 mask+0: 1(-5.675,5.2) 16(-5.675,-5.2) 27(5.675,-5.2) 42(5.675,5.2)
  rrect25% 1.05x0.4 smd paste+0 mask+0: 2(-5.675,4.225) 3(-5.675,3.575) 4(-5.675,2.925) 5(-5.675,2.275) 6(-5.675,1.625) 7(-5.675,0.975) 8(-5.675,0.325) 9(-5.675,-0.325) 10(-5.675,-0.975) 11(-5.675,-1.625) 12(-5.675,-2.275) 13(-5.675,-2.925) 14(-5.675,-3.575) 15(-5.675,-4.225) 28(5.675,-4.225) 29(5.675,-3.575) 30(5.675,-2.925) 31(5.675,-2.275) 32(5.675,-1.625) 33(5.675,-0.975) 34(5.675,-0.325) 35(5.675,0.325) 36(5.675,0.975) 37(5.675,1.625) 38(5.675,2.275) 39(5.675,2.925) 40(5.675,3.575) 41(5.675,4.225)
  rrect25% 0.4x1.05 smd paste+0 mask+0: 17(-1.935,-5.675) 18(-1.285,-5.675) 19(-0.635,-5.675) 20(0.015,-5.675) 21(0.665,-5.675) 22(1.315,-5.675) 23(1.965,-5.675) 24(2.615,-5.675) 25(3.265,-5.675) 26(3.915,-5.675) 43(3.915,5.675) 44(3.265,5.675) 45(2.615,5.675) 46(1.965,5.675) 47(1.315,5.675) 48(0.665,5.675) 49(0.015,5.675) 50(-0.635,5.675) 51(-1.285,5.675) 52(-1.935,5.675)
  silkscreen extent -6.9,-6.05 4.77,6.05, body extent -6,-6 6,6, height 1
SMAF [mm] "SMD, 2-Leads, Body 3.8x2.5mm"
  rect 1.24x1.89 smd: 1(-2.04,0) 2(2.04,0)
  silkscreen extent -3.4,-1.3 2.8,1.3, body extent -2.35,-1.25 2.35,1.25, height 1
SOD-123 [mm] "On Semi recommended land pattern"
  rect 0.915x1.22 smd: 1(-1.637,0) 2(1.637,0)
  silkscreen extent -2.74,-1.17 2.03,1.17, body extent -1.93,-0.9 1.93,0.9, height 1.35
TDK_ACM2520-2P [mm] "SMD, 4-Leads, Body 2.5x2mm"
  rect 0.8x0.4 smd: 1(-1.15,0.65) 2(-1.15,-0.65) 3(1.15,-0.65) 4(1.15,0.65)
  silkscreen extent -1.45,-1.2 1.45,1.4, body extent -1.35,-1.1 1.35,1.1, height 1.3
Wurth_760390013 [mil] "Wurth"
  rect 44x38 smd: 1(-180,100) 2(-180,0) 3(-180,-100) 4(180,-100) 5(180,0) 6(180,100)
  silkscreen extent -190,-133 85,145, body extent -198,-135 198,130, height 166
